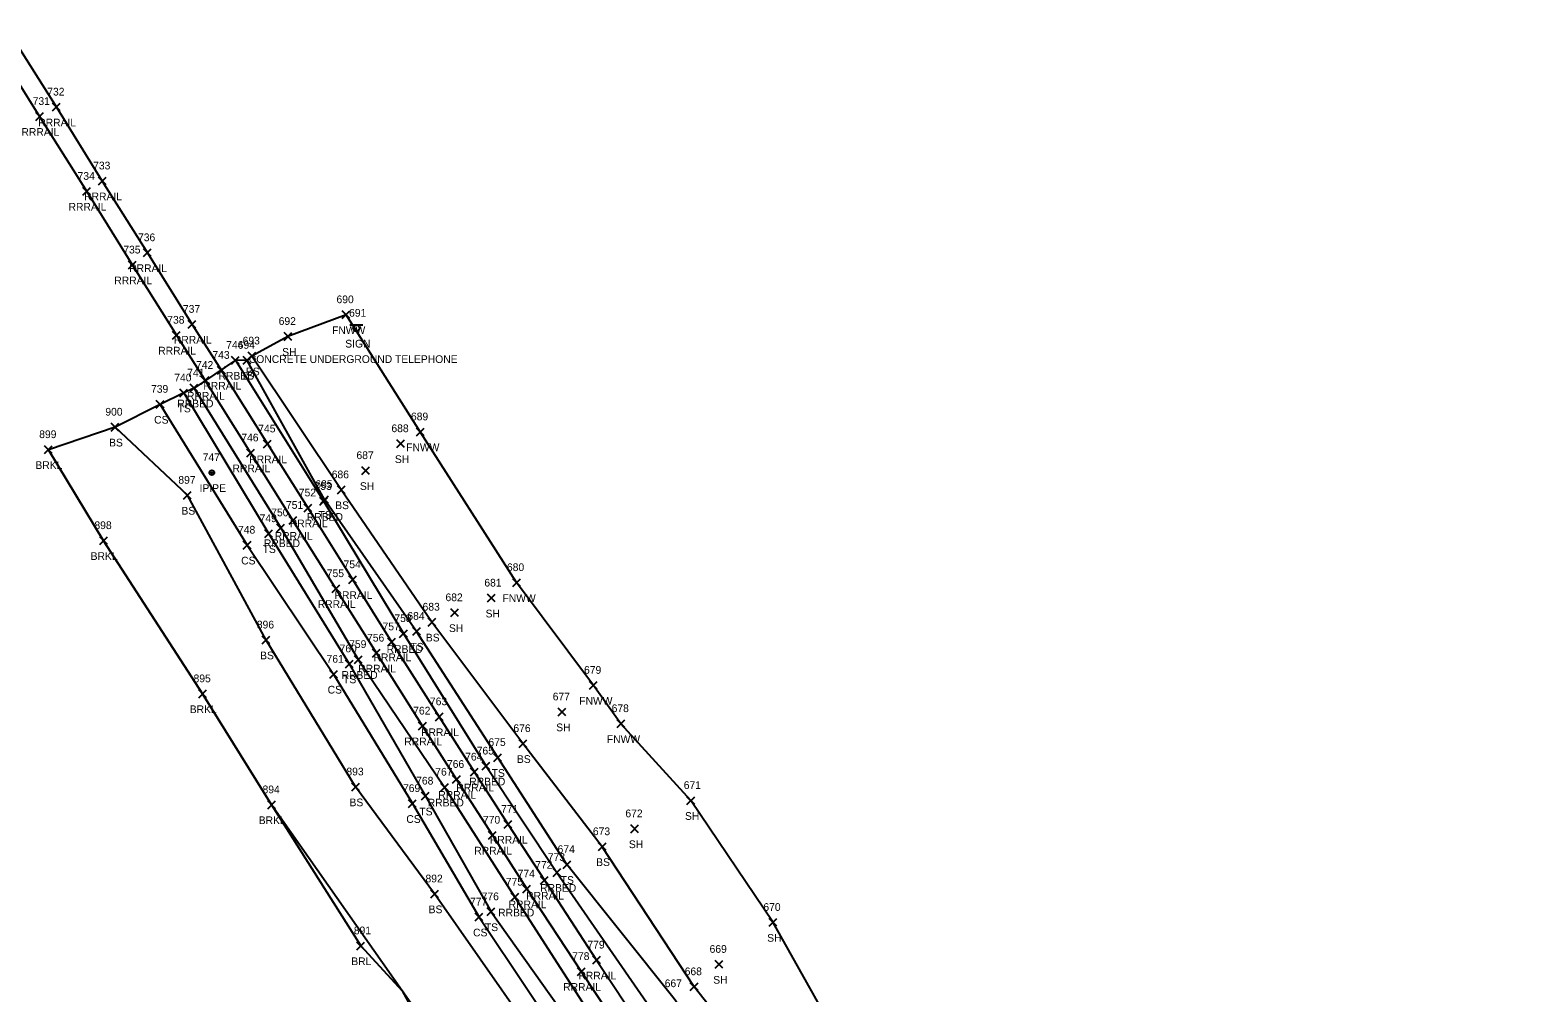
# Model space of a CAD drawing. Extents: x 1679360 to 1685861, y 903420 to 905946.
# Drawn here: x 1679580 to 1679970.7, y 904166 to 904415.5 of the extents above; entities that cross this region are included whole.
import ezdxf

# ---------------------------------------------------------------- set-up
doc = ezdxf.new("R2010")
doc.units = 0
for name, color, linetype in [('L_A', 7, 'Continuous'), ('L_I', 7, 'Continuous'), ('L_TIC', 7, 'Continuous'), ('LAWE', 7, 'Continuous'), ('LELB', 7, 'Continuous'), ('LFNC', 7, 'Continuous'), ('LSOGP', 7, 'Continuous'), ('M_A', 7, 'Continuous'), ('M_I', 7, 'Continuous'), ('MPIP', 7, 'Continuous'), ('R_A', 7, 'Continuous'), ('R_I', 7, 'Continuous'), ('R_TIC', 7, 'Continuous'), ('RR', 7, 'Continuous'), ('RRB', 7, 'Continuous'), ('S_A', 7, 'Continuous'), ('S_C', 7, 'Continuous'), ('S_I', 7, 'Continuous'), ('SSGN', 7, 'Continuous')]:
    doc.layers.add(name, color=color, linetype=linetype)

msp = doc.modelspace()

# ---------------------------------------------------------------- linework, layer by layer
at = {"layer": 'L_TIC'}
for points in [[(1679660.91, 904340.69), (1679662.91, 904342.69)], [(1679662.91, 904340.69), (1679660.91, 904342.69)], [(1679645.84, 904335.06), (1679647.84, 904337.06)], [(1679647.84, 904335.06), (1679645.84, 904337.06)], [(1679635.23, 904328.88), (1679637.23, 904330.88)], [(1679637.23, 904328.88), (1679635.23, 904330.88)], [(1679636.49, 904330), (1679638.49, 904332)], [(1679638.49, 904330), (1679636.49, 904332)], [(1679618.82, 904320.42), (1679620.82, 904322.42)], [(1679620.82, 904320.42), (1679618.82, 904322.42)], [(1679612.72, 904317.48), (1679614.72, 904319.48)], [(1679614.72, 904317.48), (1679612.72, 904319.48)], [(1679601.04, 904311.56), (1679603.04, 904313.56)], [(1679603.04, 904311.56), (1679601.04, 904313.56)], [(1679680.13, 904310.34), (1679682.13, 904312.34)], [(1679682.13, 904310.34), (1679680.13, 904312.34)], [(1679583.74, 904305.73), (1679585.74, 904307.73)], [(1679585.74, 904305.73), (1679583.74, 904307.73)], [(1679675.06, 904307.27), (1679677.06, 904309.27)], [(1679677.06, 904307.27), (1679675.06, 904309.27)], [(1679665.99, 904300.29), (1679667.99, 904302.29)], [(1679667.99, 904300.29), (1679665.99, 904302.29)], [(1679619.79, 904293.9), (1679621.79, 904295.9)], [(1679621.79, 904293.9), (1679619.79, 904295.9)], [(1679655.34, 904292.81), (1679657.34, 904294.81)], [(1679657.34, 904292.81), (1679655.34, 904294.81)], [(1679659.64, 904295.32), (1679661.64, 904297.32)], [(1679661.64, 904295.32), (1679659.64, 904297.32)], [(1679598.05, 904282.15), (1679600.05, 904284.15)], [(1679600.05, 904282.15), (1679598.05, 904284.15)], [(1679635.27, 904280.99), (1679637.27, 904282.99)], [(1679637.27, 904280.99), (1679635.27, 904282.99)], [(1679640.86, 904283.96), (1679642.86, 904285.96)], [(1679642.86, 904283.96), (1679640.86, 904285.96)], [(1679705.09, 904271.27), (1679707.09, 904273.27)], [(1679707.09, 904271.27), (1679705.09, 904273.27)], [(1679698.57, 904267.26), (1679700.57, 904269.26)], [(1679700.57, 904267.26), (1679698.57, 904269.26)], [(1679689.07, 904263.47), (1679691.07, 904265.47)], [(1679691.07, 904263.47), (1679689.07, 904265.47)], [(1679679.19, 904258.65), (1679681.19, 904260.65)], [(1679681.19, 904258.65), (1679679.19, 904260.65)], [(1679683.13, 904261.03), (1679685.13, 904263.03)], [(1679685.13, 904261.03), (1679683.13, 904263.03)], [(1679640.18, 904256.4), (1679642.18, 904258.4)], [(1679642.18, 904256.4), (1679640.18, 904258.4)], [(1679661.72, 904250.2), (1679663.72, 904252.2)], [(1679663.72, 904250.2), (1679661.72, 904252.2)], [(1679657.68, 904247.53), (1679659.68, 904249.53)], [(1679659.68, 904247.53), (1679657.68, 904249.53)], [(1679623.73, 904242.46), (1679625.73, 904244.46)], [(1679625.73, 904242.46), (1679623.73, 904244.46)], [(1679724.99, 904244.65), (1679726.99, 904246.65)], [(1679726.99, 904244.65), (1679724.99, 904246.65)], [(1679716.86, 904237.76), (1679718.86, 904239.76)], [(1679718.86, 904237.76), (1679716.86, 904239.76)], [(1679732.13, 904234.72), (1679734.13, 904236.72)], [(1679734.13, 904234.72), (1679732.13, 904236.72)], [(1679706.73, 904229.55), (1679708.73, 904231.55)], [(1679708.73, 904229.55), (1679706.73, 904231.55)], [(1679700.21, 904225.94), (1679702.21, 904227.94)], [(1679702.21, 904225.94), (1679700.21, 904227.94)], [(1679663.35, 904218.32), (1679665.35, 904220.32)], [(1679665.35, 904218.32), (1679663.35, 904220.32)], [(1679681.47, 904215.95), (1679683.47, 904217.95)], [(1679683.47, 904215.95), (1679681.47, 904217.95)], [(1679750.24, 904214.8), (1679752.24, 904216.8)], [(1679752.24, 904214.8), (1679750.24, 904216.8)], [(1679641.61, 904213.69), (1679643.61, 904215.69)], [(1679643.61, 904213.69), (1679641.61, 904215.69)], [(1679678.07, 904214.01), (1679680.07, 904216.01)], [(1679680.07, 904214.01), (1679678.07, 904216.01)], [(1679735.69, 904207.47), (1679737.69, 904209.47)], [(1679737.69, 904207.47), (1679735.69, 904209.47)], [(1679727.27, 904202.83), (1679729.27, 904204.83)], [(1679729.27, 904202.83), (1679727.27, 904204.83)], [(1679718.12, 904198.21), (1679720.12, 904200.21)], [(1679720.12, 904198.21), (1679718.12, 904200.21)], [(1679683.84, 904190.6), (1679685.84, 904192.6)], [(1679685.84, 904190.6), (1679683.84, 904192.6)], [(1679695.37, 904184.6), (1679697.37, 904186.6)], [(1679697.37, 904184.6), (1679695.37, 904186.6)], [(1679698.46, 904185.97), (1679700.46, 904187.97)], [(1679700.46, 904185.97), (1679698.46, 904187.97)], [(1679771.54, 904183.21), (1679773.54, 904185.21)], [(1679773.54, 904183.21), (1679771.54, 904185.21)], [(1679664.71, 904177.14), (1679666.71, 904179.14)], [(1679666.71, 904177.14), (1679664.71, 904179.14)], [(1679757.57, 904172.34), (1679759.57, 904174.34)], [(1679759.57, 904172.34), (1679757.57, 904174.34)], [(1679751.11, 904166.54), (1679753.11, 904168.54)], [(1679753.11, 904166.54), (1679751.11, 904168.54)]]:
    msp.add_lwpolyline(points, dxfattribs=at)
at = {"layer": 'LAWE'}
msp.add_lwpolyline([(1679721.41, 904093.23), (1679710.28, 904118.26), (1679642.61, 904214.69), (1679624.73, 904243.46), (1679599.05, 904283.15), (1679584.74, 904306.73)], dxfattribs=at)
at = {"layer": 'LELB'}
for points in [[(1679957.35, 904067.57), (1679950.7, 904052.36), (1679948.48, 904046.41), (1679946.09, 904041.57), (1679931.01, 904039.98), (1679888.72, 904042.9), (1679856.91, 904046.05), (1679830.24, 904050.06), (1679823.69, 904055.74), (1679818.78, 904061.51), (1679813.5, 904065.59), (1679796.72, 904097.55), (1679771.59, 904129.9), (1679746.93, 904164.44), (1679719.12, 904199.21), (1679701.21, 904226.94), (1679680.19, 904259.65), (1679656.34, 904293.81), (1679636.23, 904329.88)], [(1679970.75, 904094.89), (1679956.12, 904082.48), (1679948.06, 904070.86), (1679945.89, 904046.82), (1679943.29, 904045.3), (1679931.1, 904045.75), (1679888.37, 904049.6), (1679852.38, 904057.08), (1679831.9, 904068.3), (1679818.58, 904068.02), (1679816.96, 904070.21), (1679822.07, 904077.46), (1679804.98, 904102.13), (1679779.08, 904133.42), (1679752.11, 904167.54), (1679728.27, 904203.83), (1679707.73, 904230.55), (1679684.13, 904262.03), (1679660.64, 904296.32), (1679637.49, 904331)], [(1679619.82, 904321.42), (1679641.86, 904284.96), (1679662.72, 904251.2), (1679682.47, 904216.95), (1679699.46, 904186.97), (1679725.72, 904150), (1679749.74, 904116.77), (1679771.88, 904083.62), (1679794.81, 904052.66), (1679781.37, 904055.05), (1679771.63, 904053.63), (1679751.57, 904052.46), (1679718.64, 904054.59), (1679678.1, 904056.93), (1679638.82, 904059.88), (1679596.67, 904062.24), (1679555.45, 904065.45), (1679516.04, 904068.29), (1679469.12, 904071.92)], [(1679613.72, 904318.48), (1679636.27, 904281.99), (1679658.68, 904248.53), (1679679.07, 904215.01), (1679696.37, 904185.6), (1679721.82, 904147.6), (1679745.3, 904114.19), (1679768.75, 904081.07), (1679780.23, 904064.6), (1679777.26, 904058.93), (1679769.31, 904058.16), (1679752.16, 904056.65), (1679719.29, 904057.03), (1679678.41, 904059.75), (1679639.22, 904063.11), (1679596.82, 904065.62), (1679556, 904068.19), (1679515.9, 904070.74), (1679469.14, 904074.52)], [(1679708.52, 904157.77), (1679684.84, 904191.6), (1679664.35, 904219.32), (1679641.18, 904257.4), (1679620.79, 904294.9), (1679602.04, 904312.56)]]:
    msp.add_lwpolyline(points, dxfattribs=at)
at = {"layer": 'LFNC'}
msp.add_lwpolyline([(1679733.13, 904235.72), (1679725.99, 904245.65), (1679706.09, 904272.27), (1679681.13, 904311.34), (1679661.91, 904341.69)], dxfattribs=at)
at = {"layer": 'LSOGP'}
msp.add_lwpolyline([(1679795.98, 904142.46), (1679772.54, 904184.21), (1679751.24, 904215.8), (1679733.13, 904235.72), (1679725.99, 904245.65), (1679706.09, 904272.27), (1679681.13, 904311.34), (1679661.91, 904341.69), (1679646.84, 904336.06), (1679637.49, 904331), (1679636.23, 904329.88), (1679633.2, 904329.89), (1679622.51, 904322.69), (1679619.82, 904321.42), (1679613.72, 904318.48), (1679602.04, 904312.56), (1679584.74, 904306.73), (1679599.05, 904283.15), (1679624.73, 904243.46), (1679642.61, 904214.69), (1679665.71, 904178.14), (1679676.45, 904166.48), (1679685.7, 904149.54)], dxfattribs=at)
at = {"layer": 'MPIP'}
for radius in [0.625, 0.0833]:
    msp.add_circle((1679627.1, 904300.77), radius, dxfattribs=at)
at = {"layer": 'R_TIC'}
for points in [[(1679585.83, 904394.51), (1679587.83, 904396.51)], [(1679587.83, 904394.51), (1679585.83, 904396.51)], [(1679581.48, 904392.07), (1679583.48, 904394.07)], [(1679583.48, 904392.07), (1679581.48, 904394.07)], [(1679597.72, 904375.36), (1679599.72, 904377.36)], [(1679599.72, 904375.36), (1679597.72, 904377.36)], [(1679593.69, 904372.67), (1679595.69, 904374.67)], [(1679595.69, 904372.67), (1679593.69, 904374.67)], [(1679609.4, 904356.76), (1679611.4, 904358.76)], [(1679611.4, 904356.76), (1679609.4, 904358.76)], [(1679605.53, 904353.58), (1679607.53, 904355.58)], [(1679607.53, 904353.58), (1679605.53, 904355.58)], [(1679620.98, 904338.21), (1679622.98, 904340.21)], [(1679622.98, 904338.21), (1679620.98, 904340.21)], [(1679616.92, 904335.39), (1679618.92, 904337.39)], [(1679618.92, 904335.39), (1679616.92, 904337.39)], [(1679632.2, 904328.89), (1679634.2, 904330.89)], [(1679634.2, 904328.89), (1679632.2, 904330.89)], [(1679628.61, 904326.28), (1679630.61, 904328.28)], [(1679630.61, 904326.28), (1679628.61, 904328.28)], [(1679621.51, 904321.69), (1679623.51, 904323.69)], [(1679623.51, 904321.69), (1679621.51, 904323.69)], [(1679624.38, 904323.68), (1679626.38, 904325.68)], [(1679626.38, 904323.68), (1679624.38, 904325.68)], [(1679636.17, 904304.88), (1679638.17, 904306.88)], [(1679638.17, 904304.88), (1679636.17, 904306.88)], [(1679640.51, 904307.21), (1679642.51, 904309.21)], [(1679642.51, 904307.21), (1679640.51, 904309.21)], [(1679651.01, 904290.62), (1679653.01, 904292.62)], [(1679653.01, 904290.62), (1679651.01, 904292.62)], [(1679655.09, 904292.31), (1679657.09, 904294.31)], [(1679657.09, 904292.31), (1679655.09, 904294.31)], [(1679643.95, 904285.47), (1679645.95, 904287.47)], [(1679645.95, 904285.47), (1679643.95, 904287.47)], [(1679647.12, 904287.39), (1679649.12, 904289.39)], [(1679649.12, 904287.39), (1679647.12, 904289.39)], [(1679658.26, 904269.71), (1679660.26, 904271.71)], [(1679660.26, 904269.71), (1679658.26, 904271.71)], [(1679662.62, 904272.03), (1679664.62, 904274.03)], [(1679664.62, 904272.03), (1679662.62, 904274.03)], [(1679675.78, 904258.06), (1679677.78, 904260.06)], [(1679677.78, 904258.06), (1679675.78, 904260.06)], [(1679672.71, 904255.91), (1679674.71, 904257.91)], [(1679674.71, 904255.91), (1679672.71, 904257.91)], [(1679664.07, 904251.34), (1679666.07, 904253.34)], [(1679666.07, 904251.34), (1679664.07, 904253.34)], [(1679668.75, 904253), (1679670.75, 904255)], [(1679670.75, 904253), (1679668.75, 904255)], [(1679680.7, 904234.1), (1679682.7, 904236.1)], [(1679682.7, 904234.1), (1679680.7, 904236.1)], [(1679685.04, 904236.5), (1679687.04, 904238.5)], [(1679687.04, 904236.5), (1679685.04, 904238.5)], [(1679697.16, 904223.73), (1679699.16, 904225.73)], [(1679699.16, 904223.73), (1679697.16, 904225.73)], [(1679689.51, 904220.27), (1679691.51, 904222.27)], [(1679691.51, 904220.27), (1679689.51, 904222.27)], [(1679694.17, 904222.17), (1679696.17, 904224.17)], [(1679696.17, 904222.17), (1679694.17, 904224.17)], [(1679686.42, 904218.26), (1679688.42, 904220.26)], [(1679688.42, 904218.26), (1679686.42, 904220.26)], [(1679702.86, 904208.63), (1679704.86, 904210.63)], [(1679704.86, 904208.63), (1679702.86, 904210.63)], [(1679698.82, 904205.81), (1679700.82, 904207.81)], [(1679700.82, 904205.81), (1679698.82, 904207.81)], [(1679715.55, 904196.16), (1679717.55, 904198.16)], [(1679717.55, 904196.16), (1679715.55, 904198.16)], [(1679707.73, 904191.88), (1679709.73, 904193.88)], [(1679709.73, 904191.88), (1679707.73, 904193.88)], [(1679712.28, 904194.13), (1679714.28, 904196.13)], [(1679714.28, 904194.13), (1679712.28, 904196.13)], [(1679704.66, 904189.77), (1679706.66, 904191.77)], [(1679706.66, 904189.77), (1679704.66, 904191.77)], [(1679725.81, 904173.45), (1679727.81, 904175.45)], [(1679727.81, 904173.45), (1679725.81, 904175.45)], [(1679721.86, 904170.49), (1679723.86, 904172.49)], [(1679723.86, 904170.49), (1679721.86, 904172.49)]]:
    msp.add_lwpolyline(points, dxfattribs=at)
at = {"layer": 'RR'}
for points in [[(1679570.12, 904412.73), (1679582.48, 904393.07), (1679594.69, 904373.67), (1679606.53, 904354.58), (1679617.92, 904336.39), (1679625.38, 904324.68), (1679637.17, 904305.88), (1679648.12, 904288.39), (1679659.26, 904270.71), (1679669.75, 904254), (1679681.7, 904235.1), (1679690.51, 904221.27), (1679699.82, 904206.81), (1679708.73, 904192.88), (1679722.86, 904171.49), (1679733.8, 904154.92)], [(1679574.22, 904415.45), (1679586.83, 904395.51), (1679598.72, 904376.36), (1679610.4, 904357.76), (1679621.98, 904339.21), (1679629.61, 904327.28), (1679641.51, 904308.21), (1679652.01, 904291.62), (1679663.62, 904273.03), (1679673.71, 904256.91), (1679686.04, 904237.5), (1679695.17, 904223.17), (1679703.86, 904209.63), (1679713.28, 904195.13), (1679726.81, 904174.45), (1679738.46, 904156.9)]]:
    msp.add_lwpolyline(points, dxfattribs=at)
at = {"layer": 'RRB'}
for points in [[(1679633.2, 904329.89), (1679656.09, 904293.31), (1679676.78, 904259.06), (1679698.16, 904224.73), (1679716.55, 904197.16), (1679742.3, 904159.89), (1679765.39, 904125.58), (1679788.39, 904092.22), (1679811.33, 904062.99), (1679819.97, 904050.18)], [(1679622.51, 904322.69), (1679644.95, 904286.47), (1679665.07, 904252.34), (1679687.42, 904219.26), (1679705.66, 904190.77), (1679730.04, 904152.75), (1679754.13, 904119.39), (1679776.83, 904086.3), (1679798.02, 904055.8), (1679804.41, 904048.47)]]:
    msp.add_lwpolyline(points, dxfattribs=at)
at = {"layer": 'SSGN'}
for p, q in [((1679662.9, 904339.05), (1679666.23, 904339.05)), ((1679664.55, 904338.22), (1679664.55, 904338.22))]:
    msp.add_line(p, q, dxfattribs=at)
msp.add_circle((1679664.55, 904338.22), 0.833, dxfattribs=at)

# ---------------------------------------------------------------- texts
at = {"layer": 'L_A'}
for s, p in [('FNWW', (1679658.26, 904336.69)), ('SH', (1679645.33, 904331.06)), ('TS', (1679634.64, 904324.88)), ('BS', (1679635.94, 904326)), ('TS', (1679618.23, 904316.42)), ('CS', (1679612.16, 904313.48)), ('BS', (1679600.48, 904307.56)), ('FNWW', (1679677.47, 904306.34)), ('BRKL', (1679581.38, 904301.73)), ('SH', (1679674.55, 904303.27)), ('SH', (1679665.48, 904296.29)), ('BS', (1679619.23, 904289.9)), ('TS', (1679654.75, 904288.81)), ('BS', (1679659.08, 904291.32)), ('BRKL', (1679595.7, 904278.15)), ('CS', (1679634.71, 904276.99)), ('TS', (1679640.27, 904279.96)), ('FNWW', (1679702.43, 904267.27)), ('SH', (1679698.06, 904263.26)), ('SH', (1679688.56, 904259.47)), ('TS', (1679678.6, 904254.65)), ('BS', (1679682.57, 904257.03)), ('BS', (1679639.62, 904252.4)), ('TS', (1679661.13, 904246.2)), ('CS', (1679657.12, 904243.53)), ('BRKL', (1679621.38, 904238.46)), ('FNWW', (1679722.33, 904240.65)), ('SH', (1679716.35, 904233.76)), ('FNWW', (1679729.48, 904230.72)), ('BS', (1679706.17, 904225.55)), ('TS', (1679699.62, 904221.94)), ('BS', (1679662.79, 904214.32)), ('TS', (1679680.88, 904211.95)), ('SH', (1679749.73, 904210.8)), ('BRKL', (1679639.26, 904209.69)), ('CS', (1679677.51, 904210.01)), ('SH', (1679735.18, 904203.47)), ('BS', (1679726.71, 904198.83)), ('TS', (1679717.53, 904194.21)), ('BS', (1679683.28, 904186.6)), ('CS', (1679694.81, 904180.6)), ('TS', (1679697.87, 904181.97)), ('SH', (1679771.03, 904179.21)), ('BRL', (1679663.25, 904173.14)), ('SH', (1679757.05, 904168.34))]:
    msp.add_text(s, height=2, dxfattribs=at).set_placement(p)
at = {"layer": 'L_I'}
for s, p in [('690', (1679659.42, 904344.69)), ('692', (1679644.43, 904339.06)), ('694', (1679633.82, 904332.88)), ('693', (1679635.09, 904334)), ('740', (1679617.38, 904324.42)), ('739', (1679611.35, 904321.48)), ('900', (1679599.51, 904315.56)), ('689', (1679678.71, 904314.34)), ('899', (1679582.37, 904309.73)), ('688', (1679673.65, 904311.27)), ('687', (1679664.59, 904304.29)), ('897', (1679618.43, 904297.9)), ('685', (1679653.93, 904296.81)), ('686', (1679658.18, 904299.32)), ('898', (1679596.69, 904286.15)), ('748', (1679633.9, 904284.99)), ('749', (1679639.49, 904287.96)), ('680', (1679703.59, 904275.27)), ('681', (1679697.73, 904271.26)), ('682', (1679687.66, 904267.47)), ('684', (1679677.78, 904262.65)), ('683', (1679681.72, 904265.03)), ('896', (1679638.77, 904260.4)), ('760', (1679660.22, 904254.2)), ('761', (1679656.84, 904251.53)), ('895', (1679622.37, 904246.46)), ('679', (1679723.57, 904248.65)), ('677', (1679715.45, 904241.76)), ('678', (1679730.72, 904238.72)), ('676', (1679705.26, 904233.55)), ('675', (1679698.8, 904229.94)), ('893', (1679661.99, 904222.32)), ('768', (1679680.06, 904219.95)), ('671', (1679749.4, 904218.8)), ('894', (1679640.25, 904217.69)), ('769', (1679676.65, 904218.01)), ('672', (1679734.28, 904211.47)), ('673', (1679725.86, 904206.83)), ('674', (1679716.71, 904202.21)), ('892', (1679682.48, 904194.6)), ('777', (1679694.01, 904188.6)), ('776', (1679697.04, 904189.97)), ('670', (1679770.04, 904187.21)), ('891', (1679663.91, 904181.14)), ('669', (1679756.1, 904176.34)), ('668', (1679749.65, 904170.54)), ('667', (1679744.47, 904167.44))]:
    msp.add_text(s, height=2, dxfattribs=at).set_placement(p)
at = {"layer": 'M_A'}
msp.add_text('IPIPE', height=2, dxfattribs=at).set_placement((1679623.93, 904295.77))
at = {"layer": 'M_I'}
msp.add_text('747', height=2, dxfattribs=at).set_placement((1679624.73, 904303.77))
at = {"layer": 'R_A'}
for s, p in [('RRRAIL', (1679582.12, 904390.51)), ('RRRAIL', (1679577.77, 904388.07)), ('RRRAIL', (1679594.01, 904371.36)), ('RRRAIL', (1679589.98, 904368.67)), ('RRRAIL', (1679605.69, 904352.76)), ('RRRAIL', (1679601.83, 904349.58)), ('RRRAIL', (1679617.27, 904334.21)), ('RRRAIL', (1679613.21, 904331.39)), ('RRBED', (1679628.84, 904324.89)), ('RRRAIL', (1679624.91, 904322.28)), ('RRBED', (1679618.16, 904317.69)), ('RRRAIL', (1679620.67, 904319.68)), ('RRRAIL', (1679632.46, 904300.88)), ('RRRAIL', (1679636.8, 904303.21)), ('RRRAIL', (1679647.3, 904286.62)), ('RRBED', (1679651.73, 904288.31)), ('RRBED', (1679640.6, 904281.47)), ('RRRAIL', (1679643.41, 904283.39)), ('RRRAIL', (1679654.56, 904265.71)), ('RRRAIL', (1679658.91, 904268.03)), ('RRBED', (1679672.42, 904254.06)), ('RRRAIL', (1679669, 904251.91)), ('RRBED', (1679660.72, 904247.34)), ('RRRAIL', (1679665.04, 904249)), ('RRRAIL', (1679681.33, 904232.5)), ('RRRAIL', (1679676.99, 904230.1)), ('RRBED', (1679693.81, 904219.73)), ('RRRAIL', (1679685.8, 904216.27)), ('RRRAIL', (1679690.46, 904218.17)), ('RRBED', (1679683.06, 904214.26)), ('RRRAIL', (1679699.15, 904204.63)), ('RRRAIL', (1679695.11, 904201.81)), ('RRBED', (1679712.19, 904192.16)), ('RRRAIL', (1679704.02, 904187.88)), ('RRRAIL', (1679708.57, 904190.13)), ('RRBED', (1679701.31, 904185.77)), ('RRRAIL', (1679722.1, 904169.45)), ('RRRAIL', (1679718.16, 904166.49))]:
    msp.add_text(s, height=2, dxfattribs=at).set_placement(p)
at = {"layer": 'R_I'}
for s, p in [('732', (1679584.46, 904398.51)), ('731', (1679580.68, 904396.07)), ('733', (1679596.35, 904379.36)), ('734', (1679592.32, 904376.67)), ('736', (1679607.98, 904360.76)), ('735', (1679604.17, 904357.58)), ('737', (1679619.62, 904342.21)), ('738', (1679615.56, 904339.39)), ('744', (1679630.83, 904332.89)), ('743', (1679627.25, 904330.28)), ('741', (1679620.72, 904325.69)), ('742', (1679623.01, 904327.68)), ('746', (1679634.75, 904308.88)), ('745', (1679639.14, 904311.21)), ('752', (1679649.65, 904294.62)), ('753', (1679653.73, 904296.31)), ('750', (1679642.5, 904289.47)), ('751', (1679646.32, 904291.39)), ('755', (1679656.9, 904273.71)), ('754', (1679661.25, 904276.03)), ('758', (1679674.42, 904262.06)), ('757', (1679671.35, 904259.91)), ('759', (1679662.7, 904255.34)), ('756', (1679667.34, 904257)), ('762', (1679679.29, 904238.1)), ('763', (1679683.63, 904240.5)), ('765', (1679695.75, 904227.73)), ('766', (1679688.04, 904224.27)), ('764', (1679692.76, 904226.17)), ('767', (1679685.01, 904222.26)), ('771', (1679702.07, 904212.63)), ('770', (1679697.37, 904209.81)), ('773', (1679714.18, 904200.16)), ('774', (1679706.37, 904195.88)), ('772', (1679710.92, 904198.13)), ('775', (1679703.3, 904193.77)), ('779', (1679724.44, 904177.45)), ('778', (1679720.5, 904174.49))]:
    msp.add_text(s, height=2, dxfattribs=at).set_placement(p)
at = {"layer": 'S_A'}
msp.add_text('SIGN', height=2, dxfattribs=at).set_placement((1679661.68, 904333.2))
at = {"layer": 'S_C'}
msp.add_text('CONCRETE UNDERGROUND TELEPHONE', height=2, dxfattribs=at).set_placement((1679636.7, 904329.2))
at = {"layer": 'S_I'}
msp.add_text('691', height=2, dxfattribs=at).set_placement((1679662.68, 904341.2))

doc.saveas('drawing.dxf')
